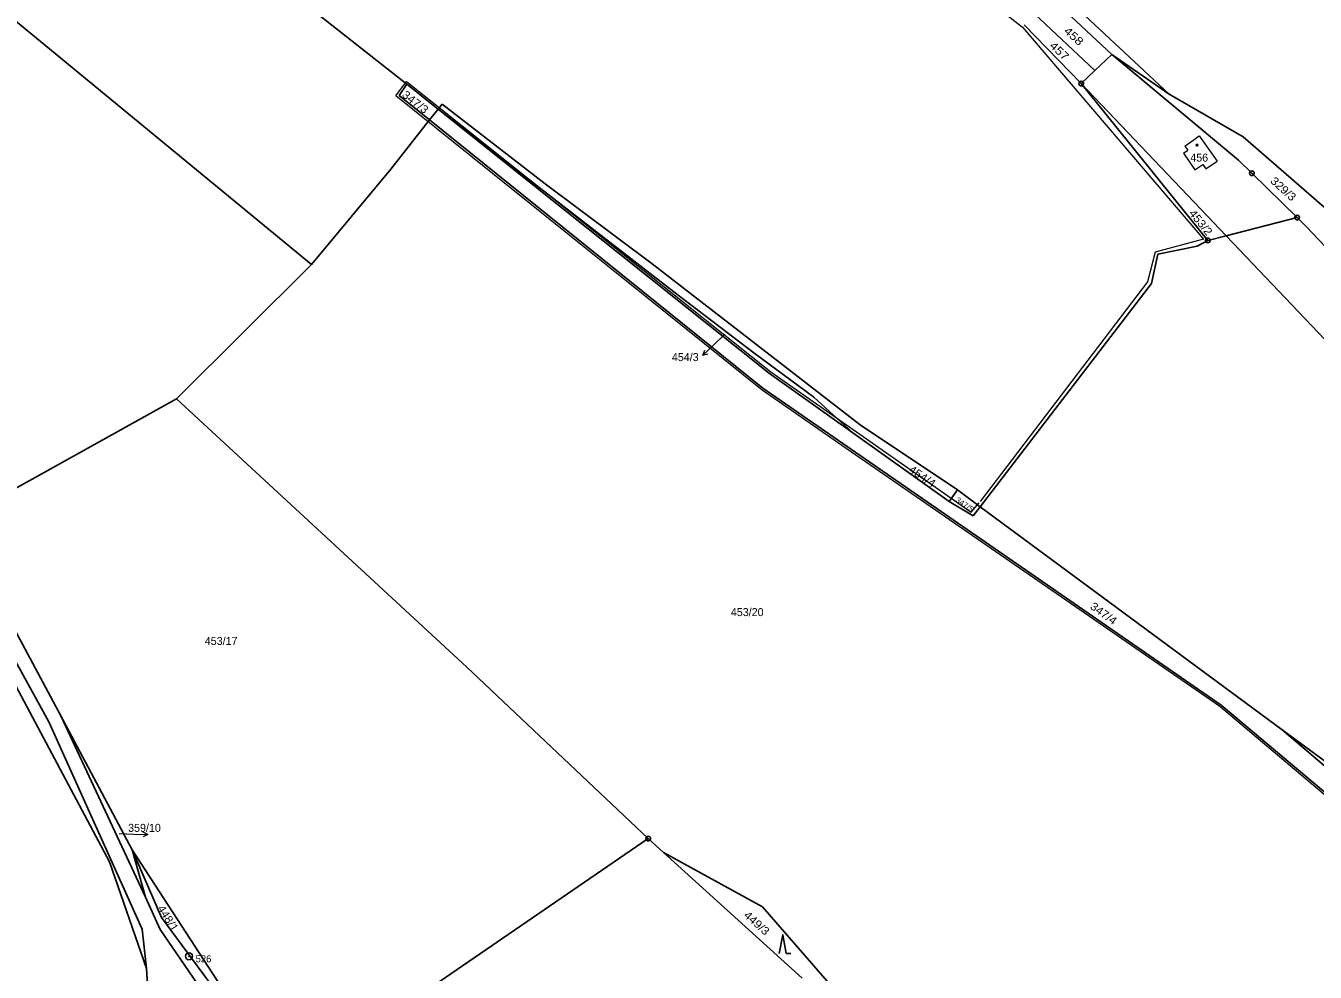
# Model space of a CAD drawing. Extents: x -633485 to -630509, y -1112692 to -1108818.
# Drawn here: x -632971.5 to -632697.5, y -1111243.4 to -1111042.2 of the extents above; entities that cross this region are included whole.
import ezdxf
from ezdxf.enums import TextEntityAlignment as Align

# ---------------------------------------------------------------- set-up
doc = ezdxf.new("R2010")
doc.units = 0
doc.header["$LTSCALE"] = 0.68
for name, color, linetype, lineweight in [('1', 7, 'Continuous', 25), ('3', 7, 'Continuous', 25), ('4', 7, 'Continuous', 13), ('5', 7, 'Continuous', 25), ('7', 7, 'Continuous', 13), ('8', 7, 'Continuous', 25)]:
    doc.layers.add(name, color=color, linetype=linetype, lineweight=lineweight)
doc.layers.add('2', color=7, linetype='Continuous')

msp = doc.modelspace()

# ---------------------------------------------------------------- linework, layer by layer
at = {"layer": '1'}
for p, q in [((-633002.13, -1111017.81), (-632910.74, -1111092.95)), ((-632770.49, -1111017.61), (-632728.49, -1111056.78)), ((-632917.06, -1111033.7), (-632890.54, -1111054.64)), ((-632753.65, -1111036.12), (-632740.71, -1111048.31)), ((-632757.13, -1111039.73), (-632744.32, -1111051.75)), ((-632759.36, -1111042.03), (-632747.21, -1111054.51)), ((-632744.32, -1111051.75), (-632740.71, -1111048.31)), ((-632740.71, -1111048.31), (-632728.49, -1111056.78)), ((-632740.71, -1111048.31), (-632713.8, -1111070.76)), ((-632747.21, -1111054.51), (-632744.32, -1111051.75)), ((-632892.12, -1111057.07), (-632890.54, -1111054.64)), ((-632890.54, -1111054.64), (-632883.89, -1111059.95)), ((-632747.21, -1111054.51), (-632723.18, -1111079.71)), ((-632747.21, -1111054.51), (-632720.33, -1111087.86)), ((-632892.12, -1111057.07), (-632885.73, -1111062.21)), ((-632728.49, -1111056.78), (-632712.8, -1111065.81)), ((-632885.73, -1111062.21), (-632883.89, -1111059.95)), ((-632883.89, -1111059.95), (-632883, -1111058.86)), ((-632883.89, -1111059.95), (-632833.14, -1111099.26)), ((-632883.89, -1111059.95), (-632813.47, -1111116.12)), ((-632883, -1111058.86), (-632861.13, -1111075.81)), ((-632893.95, -1111072.69), (-632885.73, -1111062.21)), ((-632885.73, -1111062.21), (-632814.86, -1111119.25)), ((-632712.8, -1111065.81), (-632695.58, -1111080.8)), ((-632713.8, -1111070.76), (-632710.94, -1111073.56)), ((-632910.74, -1111092.95), (-632893.95, -1111072.69)), ((-632710.94, -1111073.56), (-632701.34, -1111082.98)), ((-632861.13, -1111075.81), (-632838.38, -1111092.85)), ((-632723.18, -1111079.71), (-632716.4, -1111086.85)), ((-632716.4, -1111086.85), (-632701.34, -1111082.98)), ((-632701.34, -1111082.98), (-632699.4, -1111084.88)), ((-632699.4, -1111084.88), (-632681.52, -1111103.88)), ((-632722.6, -1111089.07), (-632720.33, -1111087.86)), ((-632720.33, -1111087.86), (-632716.4, -1111086.85)), ((-632716.4, -1111086.85), (-632687.58, -1111117.22)), ((-632732.26, -1111096.99), (-632730.94, -1111090.74)), ((-632730.94, -1111090.74), (-632722.6, -1111089.07)), ((-632939.43, -1111121.5), (-632910.74, -1111092.95)), ((-632838.38, -1111092.85), (-632794.18, -1111127.05)), ((-632768.68, -1111144.43), (-632732.26, -1111096.99)), ((-632833.14, -1111099.26), (-632816.79, -1111111.75)), ((-632816.79, -1111111.75), (-632804, -1111121.17)), ((-632813.47, -1111116.12), (-632795.72, -1111128.75)), ((-632814.86, -1111119.25), (-632717.45, -1111186.58)), ((-632985.88, -1111147.3), (-632939.43, -1111121.5)), ((-632939.43, -1111121.5), (-632877.8, -1111178.57)), ((-632804, -1111121.17), (-632795.72, -1111128.75)), ((-632795.72, -1111128.75), (-632775.24, -1111143.32)), ((-632794.18, -1111127.05), (-632773.5, -1111140.87)), ((-632995.74, -1111137.18), (-632966.62, -1111190.16)), ((-632775.24, -1111143.32), (-632773.5, -1111140.87)), ((-632773.5, -1111140.87), (-632768.68, -1111144.43)), ((-632775.24, -1111143.32), (-632770.16, -1111146.4)), ((-632770.16, -1111146.4), (-632768.68, -1111144.43)), ((-632768.68, -1111144.43), (-632704.48, -1111191.83)), ((-632982.45, -1111165.99), (-632953.67, -1111219.9)), ((-632975.92, -1111166.63), (-632964.06, -1111188.88)), ((-632877.8, -1111178.57), (-632839.23, -1111214.96)), ((-632717.45, -1111186.58), (-632659.74, -1111235.34)), ((-632964.06, -1111188.88), (-632946.08, -1111227.45)), ((-632964.06, -1111188.88), (-632948.87, -1111217.37)), ((-632966.62, -1111190.16), (-632946.79, -1111234.19)), ((-632704.48, -1111191.83), (-632655.79, -1111233.58)), ((-632704.48, -1111191.83), (-632653.53, -1111229.45)), ((-632916.13, -1111267.62), (-632839.23, -1111214.96)), ((-632839.23, -1111214.96), (-632835.97, -1111217.93)), ((-632948.87, -1111217.37), (-632942.62, -1111231.76)), ((-632948.87, -1111217.37), (-632946.08, -1111227.45)), ((-632948.87, -1111217.37), (-632916.13, -1111267.62)), ((-632835.97, -1111217.93), (-632814.92, -1111229.45)), ((-632835.97, -1111217.93), (-632806.5, -1111244.62)), ((-632953.67, -1111219.9), (-632945.83, -1111242.61)), ((-632946.08, -1111227.45), (-632942.9, -1111234.26)), ((-632814.92, -1111229.45), (-632796.95, -1111250.08)), ((-632942.62, -1111231.76), (-632916.13, -1111267.62)), ((-632946.79, -1111234.19), (-632945.83, -1111242.61)), ((-632942.9, -1111234.26), (-632916.19, -1111273.37)), ((-632945.83, -1111242.61), (-632943.26, -1111283.49))]:
    msp.add_line(p, q, dxfattribs=at)
at = {"layer": '3'}
msp.add_line((-632809.9, -1111239.39), (-632808.904, -1111239.39), dxfattribs=at)
msp.add_lwpolyline([(-632809.9, -1111239.39), (-632810.65, -1111235.39), (-632811.4, -1111239.39)], dxfattribs=at)
at = {"layer": '4'}
for p, q in [((-632725.17, -1111067.84), (-632722.15, -1111065.63)), ((-632722.15, -1111065.63), (-632718.34, -1111071.01)), ((-632725.46, -1111069.34), (-632724.56, -1111068.68)), ((-632725.17, -1111067.84), (-632724.56, -1111068.68)), ((-632725.46, -1111069.34), (-632723.09, -1111072.86)), ((-632720.74, -1111072.62), (-632718.34, -1111071.01)), ((-632723.09, -1111072.86), (-632721.36, -1111071.7)), ((-632721.36, -1111071.7), (-632720.74, -1111072.62))]:
    msp.add_line(p, q, dxfattribs=at)
for points in [[(-632797.72, -1111012.6), (-632759.66, -1111042.52), (-632721.25, -1111087.58), (-632731.48, -1111090.31), (-632733.11, -1111096.65), (-632768.65, -1111143.35)], [(-632660.69, -1111235.05), (-632717.79, -1111186.93), (-632798.06, -1111131.43), (-632815.04, -1111119.67), (-632892.84, -1111057.15), (-632890.57, -1111054.06), (-632883.31, -1111059.88)], [(-632883.31, -1111059.88), (-632813.15, -1111115.75), (-632770.63, -1111145.62), (-632768.88, -1111143.58)]]:
    msp.add_lwpolyline(points, dxfattribs=at)
at = {"layer": '5'}
msp.add_circle((-632722.6168, -1111067.5892), 0.175, dxfattribs=at)
at = {"layer": '7'}
for p, q in [((-632827.589, -1111112.255), (-632826.52, -1111111.919)), ((-632945.541, -1111214.115), (-632946.524, -1111213.579))]:
    msp.add_line(p, q, dxfattribs=at)
for points in [[(-632822.93, -1111107.75), (-632825.43, -1111110.17), (-632827.589, -1111112.255), (-632827.216, -1111111.199)], [(-632951.65, -1111213.92), (-632948.54, -1111214.01), (-632945.541, -1111214.115), (-632946.559, -1111214.58)]]:
    msp.add_lwpolyline(points, dxfattribs=at)
at = {"layer": '8'}
for centre, radius in [((-632747.21, -1111054.5099), 0.5), ((-632747.21, -1111054.5099), 0.0303), ((-632710.94, -1111073.5599), 0.5), ((-632710.94, -1111073.5599), 0.0303), ((-632701.34, -1111082.9799), 0.5), ((-632701.34, -1111082.9799), 0.0303), ((-632720.33, -1111087.8599), 0.5), ((-632720.33, -1111087.8599), 0.0303), ((-632839.23, -1111214.9599), 0.5), ((-632839.23, -1111214.9599), 0.0303), ((-632936.81, -1111239.9798), 0.75), ((-632936.81, -1111239.9798), 0.03)]:
    msp.add_circle(centre, radius, dxfattribs=at)

# ---------------------------------------------------------------- texts
at = {"layer": '2'}
for s, height, rotation, width, p in [('458', 1.7, 318, 1.2, (-632751.054, -1111043.545)), ('457', 1.7, 317, 1.2, (-632754.089, -1111046.65)), ('347/3', 1.7, 322, 1.1, (-632891.691, -1111057.194)), ('329/3', 1.7, 318, 1.1, (-632707.144, -1111075.435)), ('453/2', 1.7, 309, 1.1, (-632724.44, -1111082.127)), ('454/4', 1.7, 326, 1.1, (-632784.047, -1111136.942)), ('347/5', 1.139, 326, 1.1, (-632774.029, -1111143.256)), ('347/4', 1.7, 324, 1.1, (-632745.479, -1111165.963)), ('448/1', 1.7, 302, 1.05, (-632943.57, -1111229.795)), ('449/3', 1.7, 318, 1.1, (-632819.044, -1111231.465))]:
    msp.add_text(s, height=height, rotation=rotation, dxfattribs=dict(at, width=width)).set_placement(p)
for s, p in [('456', (-632724.04, -1111071.105)), ('453/20', (-632821.66, -1111167.685)), ('453/17', (-632933.45, -1111173.815))]:
    msp.add_text(s, height=1.7, dxfattribs=at).set_placement(p)
for s, p in [('454/3', (-632831.35, -1111113.495)), ('359/10', (-632946.27, -1111213.535))]:
    msp.add_text(s, height=1.7, dxfattribs=at).set_placement(p, align=Align.CENTER)
at = {"layer": '8'}
msp.add_text('526', height=1.5, dxfattribs=at).set_placement((-632935.4, -1111241.265))

doc.saveas('drawing.dxf')
